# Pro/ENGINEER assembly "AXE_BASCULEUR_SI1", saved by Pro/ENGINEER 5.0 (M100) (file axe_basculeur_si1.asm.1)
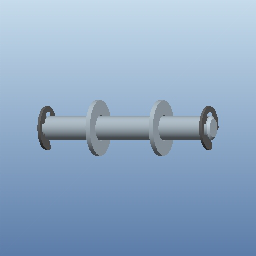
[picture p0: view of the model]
Units: millimeter Newton Second (mmNs); MM, TONNE, HOURS

Other components: AXE_BASCULEUR_SI1, ANNEAU_RADIAL-6X07, ANNEAU_RADIAL-6X07, RONDELLE_PLATE-D6, RONDELLE_PLATE-D6

Other named items: AXE_BASCULEUR, A-DROITE, A-DESSUS, A-FACE, A-R0, ACS0, ACS1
